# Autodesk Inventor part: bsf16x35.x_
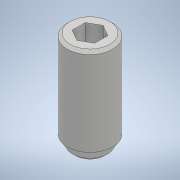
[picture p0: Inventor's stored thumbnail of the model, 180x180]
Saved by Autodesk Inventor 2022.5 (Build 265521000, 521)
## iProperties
Created: 2020-01
Part Number: bsf16x35.x_
Material: 一般
Document SubType Name: Modeling
Designer: ImaoCorp
Density: 1 g/cm^3
Appearance: 既定
Sending System: SOLIDWORKS 2018-2018316
MC: AMD64
MC_MODEL: Intel64 Family 6 Model 60 Stepping 3, GenuineIntel
OS: Windows_NT
FRU: Parasolid Version 30.0, build 310,  6- 8-2018
FORMAT: text
GUISE: transmit
KEY: bsf16x35
FILE: bsf16x35.x_t
DATE: Thu Jan 23 16:49:04 2020
Author: ImaoCorp
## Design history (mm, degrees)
feature "Base1"
node "ソリッド1"
